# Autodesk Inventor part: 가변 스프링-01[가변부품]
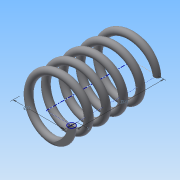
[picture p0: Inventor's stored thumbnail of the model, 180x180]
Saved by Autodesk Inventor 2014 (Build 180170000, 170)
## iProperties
Created: 2015-09
Part Number: 가변 스프링-01[가변부품]
Material: 강철, 탄소
Document SubType Name: Modeling
Designer: study
Density: 1 g/cm^3
Appearance: 반연마
Author: study
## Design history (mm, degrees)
sketch "스케치1"
  geometry: L1 (0, 0)-(11, 0); L2 (11, 0)-(11, 36.411); L3 (11, 36.411)-(0, 36.411); L4 (0, 36.411)-(0, 0); C1 r 1.5 at (11, 0)
  constraints: 8 end point, 2 parallel, 1 centre point, 1 coincident, 1 horizontal, 1 perpendicular
  dimensions: "d0" = 3 diameter of C1; "d1" = 22 diameter of L2 L4; "d2" = 36.4112 distance of L1.end L2.end (derived)
feature "코일1" sketch "스케치1" pitch "d3" = 10; turns "d5" = 5; dims "d4" = 36.4112 (= d2), "d6" = 0, angle "d7" = 90 deg, angle "d8" = 90 deg, "d9" = 0, "d10" = 0
node "작업 평면1"
sketch "스케치2"
  geometry: L1 (-12.5, 0)-(-9.5, 0) reference; 1 further point
  constraints: 1 horizontal alignment
extrude "돌출1" cut sketch "스케치2" distance "d12" = 10; taper "d13" = 0 deg
node "작업 평면2"
sketch "스케치3"
  geometry: L1 (-9.5, 0)-(-12.5, 0) reference; L2 (-9.5, 0)-(-12.5, 0) reference; 1 further point
  constraints: 2 horizontal alignment
extrude "돌출2" cut sketch "스케치3" distance "d15" = 10; taper "d16" = 0 deg
node "솔리드1"
node "절단 모서리 투영1"
node "절단 모서리 투영2"
node "절단 모서리 투영3"
other parameters: "d11" = 0, "d14" = 36.4112 (= d2)
